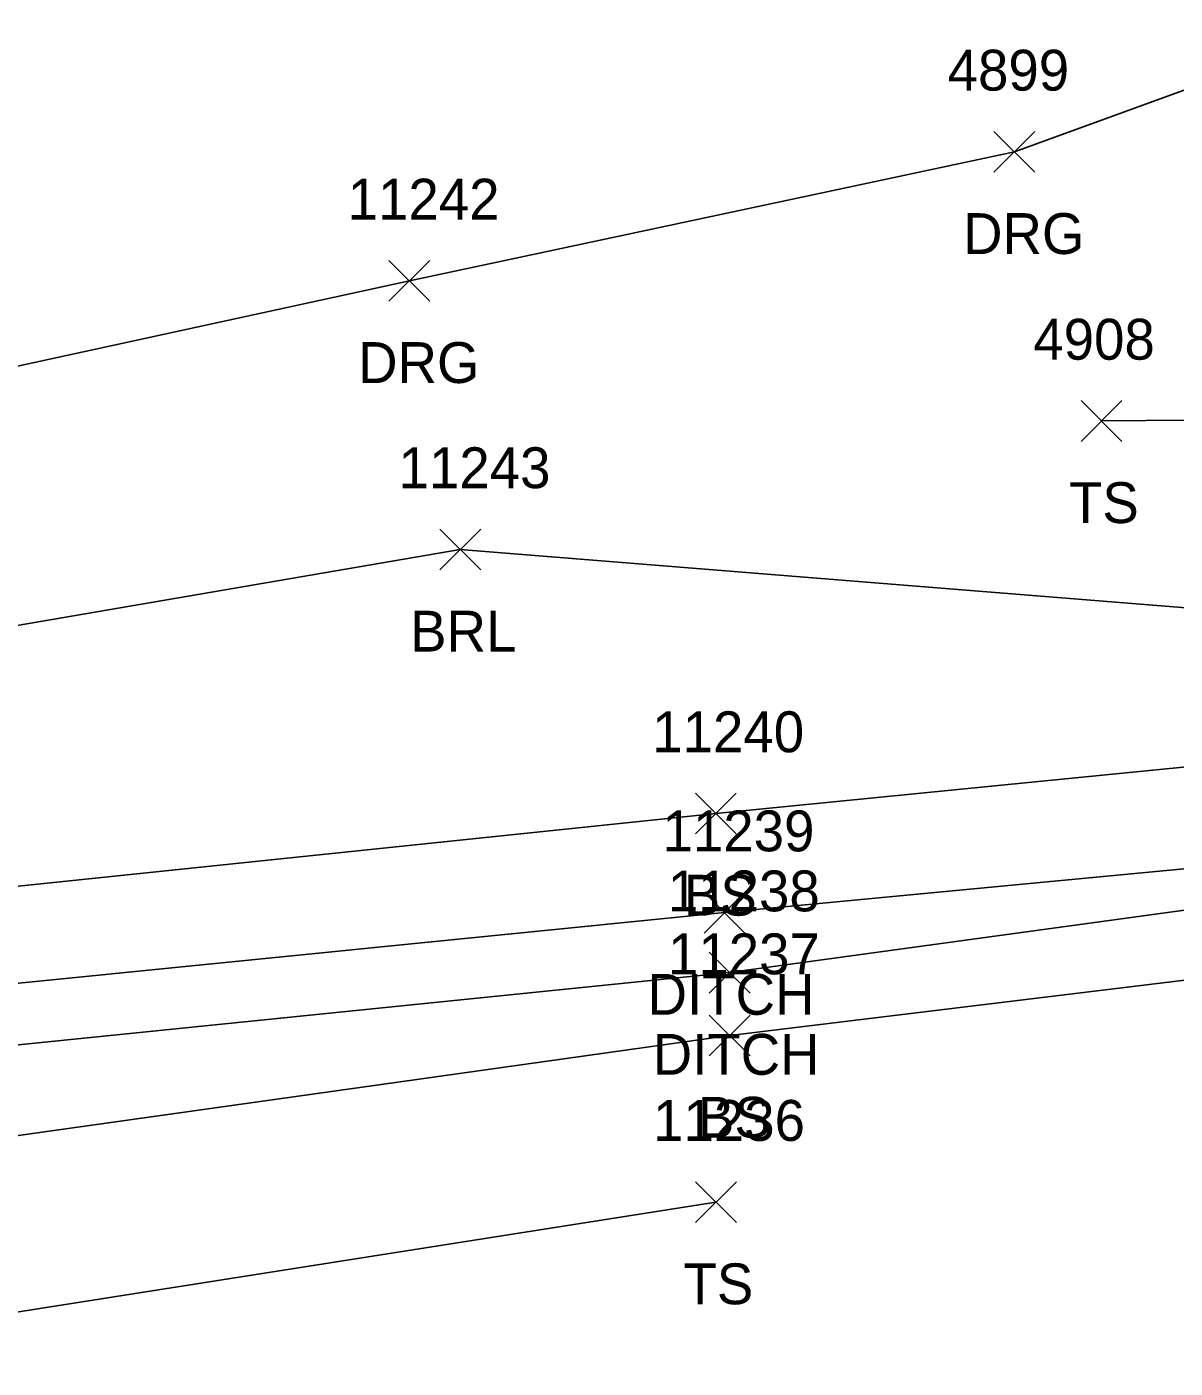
# Model space of a CAD drawing. Extents: x 1769141 to 1770911, y 735471 to 741449.
# Drawn here: x 1770541.1 to 1770597.3, y 739321.7 to 739387.3 of the extents above; entities that cross this region are included whole.
import ezdxf

# ---------------------------------------------------------------- set-up
doc = ezdxf.new("R2010")
doc.units = 0
for name, color, linetype in [('D_A', 7, 'Continuous'), ('D_I', 7, 'Continuous'), ('D_TIC', 7, 'Continuous'), ('DD', 7, 'Continuous'), ('L_A', 7, 'Continuous'), ('L_I', 7, 'Continuous'), ('L_TIC', 7, 'Continuous'), ('LABL', 7, 'Continuous'), ('LELB', 7, 'Continuous'), ('R_A', 7, 'Continuous'), ('R_I', 7, 'Continuous'), ('R_TIC', 7, 'Continuous'), ('RDG', 7, 'Continuous')]:
    doc.layers.add(name, color=color, linetype=linetype)

msp = doc.modelspace()

# ---------------------------------------------------------------- linework, layer by layer
at = {"layer": 'D_TIC'}
for points in [[(1770574.269, 739342.976), (1770576.269, 739344.976)], [(1770576.269, 739342.976), (1770574.269, 739344.976)], [(1770574.52, 739340.037), (1770576.52, 739342.037)], [(1770576.52, 739340.037), (1770574.52, 739342.037)]]:
    msp.add_lwpolyline(points, dxfattribs=at)
at = {"layer": 'DD'}
for points in [[(1770575.269, 739343.976), (1770608.234, 739347.122)], [(1770575.52, 739341.037), (1770608.405, 739345.552)], [(1770415.172, 739316.215), (1770477.653, 739329.628), (1770527.012, 739339.155), (1770575.269, 739343.976)], [(1770431.973, 739300.356), (1770479.116, 739327.34), (1770528.178, 739336.225), (1770575.52, 739341.037)]]:
    msp.add_lwpolyline(points, dxfattribs=at)
at = {"layer": 'L_TIC'}
for points in [[(1770592.726, 739367.046), (1770594.726, 739369.046)], [(1770594.726, 739367.046), (1770592.726, 739369.046)], [(1770561.338, 739360.755), (1770563.338, 739362.755)], [(1770563.338, 739360.755), (1770561.338, 739362.755)], [(1770573.843, 739347.827), (1770575.843, 739349.827)], [(1770575.843, 739347.827), (1770573.843, 739349.827)], [(1770574.526, 739336.956), (1770576.526, 739338.956)], [(1770576.526, 739336.956), (1770574.526, 739338.956)], [(1770573.854, 739328.801), (1770575.854, 739330.801)], [(1770575.854, 739328.801), (1770573.854, 739330.801)]]:
    msp.add_lwpolyline(points, dxfattribs=at)
at = {"layer": 'LABL'}
for points in [[(1770562.338, 739361.755), (1770516.076, 739353.825), (1770467.383, 739349.001), (1770427.086, 739334.57), (1770373.481, 739328.45), (1770342.031, 739325.79), (1770319.675, 739332.875), (1770306.845, 739401.56), (1770309.595, 739450.67), (1770315.731, 739476.287), (1770304.714, 739488.567)], [(1770601.731, 739358.584), (1770562.338, 739361.755)]]:
    msp.add_lwpolyline(points, dxfattribs=at)
at = {"layer": 'LELB'}
for points in [[(1770635.06, 739529.192), (1770645.307, 739529.851), (1770645.989, 739527.602), (1770639.825, 739525.766), (1770636.837, 739523.367), (1770636.3, 739517.948), (1770642.837, 739497.54), (1770651.217, 739462.014), (1770656.356, 739424.189), (1770658.198, 739376.739), (1770646.49, 739357.715), (1770639.396, 739364.656), (1770619.765, 739368.255), (1770593.726, 739368.046)], [(1770574.843, 739348.827), (1770605.786, 739351.893)], [(1770415.172, 739316.215), (1770473.946, 739339.025), (1770526.288, 739343.774), (1770574.843, 739348.827)], [(1770575.526, 739337.956), (1770609.35, 739342.073)], [(1770431.973, 739300.356), (1770480.124, 739324.455), (1770527.916, 739331.267), (1770575.526, 739337.956)], [(1770494.6, 739214.31), (1770479.626, 739221.773), (1770481.404, 739241.872), (1770460.826, 739273.271), (1770438.916, 739278.931), (1770440.873, 739299.724), (1770457.169, 739309.771), (1770482.081, 739316.502), (1770530.433, 739322.813), (1770574.854, 739329.801)]]:
    msp.add_lwpolyline(points, dxfattribs=at)
at = {"layer": 'R_TIC'}
for points in [[(1770588.461, 739380.219), (1770590.461, 739382.219)], [(1770590.461, 739380.219), (1770588.461, 739382.219)], [(1770558.845, 739373.904), (1770560.845, 739375.904)], [(1770560.845, 739373.904), (1770558.845, 739375.904)]]:
    msp.add_lwpolyline(points, dxfattribs=at)
at = {"layer": 'RDG'}
for points in [[(1770605.885, 739460.803), (1770614.092, 739421.578), (1770610.49, 739398.663), (1770602.164, 739385.835), (1770589.461, 739381.219)], [(1770559.845, 739374.904), (1770513.356, 739364.792), (1770462.64, 739364.902), (1770424.914, 739349.62), (1770371.791, 739339.332), (1770340.707, 739339.491), (1770329.563, 739379.425), (1770322.918, 739401.168), (1770331.858, 739418.344), (1770389.334, 739431.619)], [(1770559.845, 739374.904), (1770589.461, 739381.219)]]:
    msp.add_lwpolyline(points, dxfattribs=at)

# ---------------------------------------------------------------- texts
at = {"layer": 'D_A'}
for p in [(1770571.505, 739338.976), (1770571.756, 739336.037)]:
    msp.add_text('DITCH', height=2, dxfattribs=at).set_placement(p)
at = {"layer": 'D_I'}
for s, p in [('11239', (1770572.237, 739346.976)), ('11238', (1770572.497, 739344.037))]:
    msp.add_text(s, height=2, dxfattribs=at).set_placement(p)
at = {"layer": 'L_A'}
for s, p in [('TS', (1770592.135, 739363.046)), ('BRL', (1770559.881, 739356.755)), ('BS', (1770573.284, 739343.827)), ('BS', (1770573.967, 739332.956)), ('TS', (1770573.263, 739324.801))]:
    msp.add_text(s, height=2, dxfattribs=at).set_placement(p)
at = {"layer": 'L_I'}
for s, p in [('4908', (1770590.387, 739371.046)), ('11243', (1770559.314, 739364.755)), ('11240', (1770571.732, 739351.827)), ('11237', (1770572.503, 739340.956)), ('11236', (1770571.775, 739332.801))]:
    msp.add_text(s, height=2, dxfattribs=at).set_placement(p)
at = {"layer": 'R_A'}
for p in [(1770586.95, 739376.219), (1770557.334, 739369.904)]:
    msp.add_text('DRG', height=2, dxfattribs=at).set_placement(p)
at = {"layer": 'R_I'}
for s, p in [('4899', (1770586.194, 739384.219)), ('11242', (1770556.822, 739377.904))]:
    msp.add_text(s, height=2, dxfattribs=at).set_placement(p)

doc.saveas('drawing.dxf')
